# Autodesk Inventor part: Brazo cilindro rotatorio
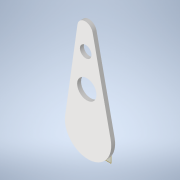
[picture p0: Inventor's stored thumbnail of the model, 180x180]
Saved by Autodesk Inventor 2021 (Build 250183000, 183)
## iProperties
Created: 2021-02
Part Number: Brazo cilindro rotatorio
Material: Genérico
Document SubType Name: Modeling
Designer: ATOUZA
Density: 1 g/cm^3
Appearance: Valor por defecto
Author: ATOUZA
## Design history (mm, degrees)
node "Plano de trabajo1"
sketch "Boceto1"
  geometry: L1 (69.16, 104.528)-(-380.578, 89.171) reference; L2 (68.477, 124.517)-(-381.26, 109.16) reference; L3 (18.307, 122.803)-(18.989, 102.815); L4 (51.827, 6.32)-(28.424, 114.916); L5 (8.751, 114.244)-(-7.19, 4.305); L6 (22.5, 0)-(18.648, 112.809); C1 r 2.5 at (11.186, 11.314) reference; C2 r 12.5 at (20.873, 47.659); C3 r 7.5 at (19.455, 89.171); C4 r 5 at (18.648, 112.809); A1 r 112.875 centre (22.5, 0) between (18.648, 112.809) and (8.679, 112.026); A2 r 30 centre (22.5, 0) between (-7.19, 4.305) and (51.827, 6.32); A3 r 10 centre (18.648, 112.809) between (28.647, 112.707) and (8.679, 112.026); 2 further points
  constraints: 9 point on circle, 8 end point, 6 centre point, 4 point on line, 4 tangent, 3 coincident, 1 horizontal alignment, 1 midpoint
  dimensions: "d0" = 60 diameter of A2; "d1" = 20 diameter of A3; "d2" = 225.75 diameter of A1; "d3" = 25 diameter of C2; "d4" = 15 diameter of C3; "d7" = 10 diameter of C4
extrude "Extrusión1" new body sketch "Boceto1" distance "d5" = 5; taper "d6" = 0 deg
sketch "Boceto2"
  geometry: 1 further point
node "Sólido1"
node "Referencia1"
node "Referencia2"
node "Referencia3"
node "Referencia4"
